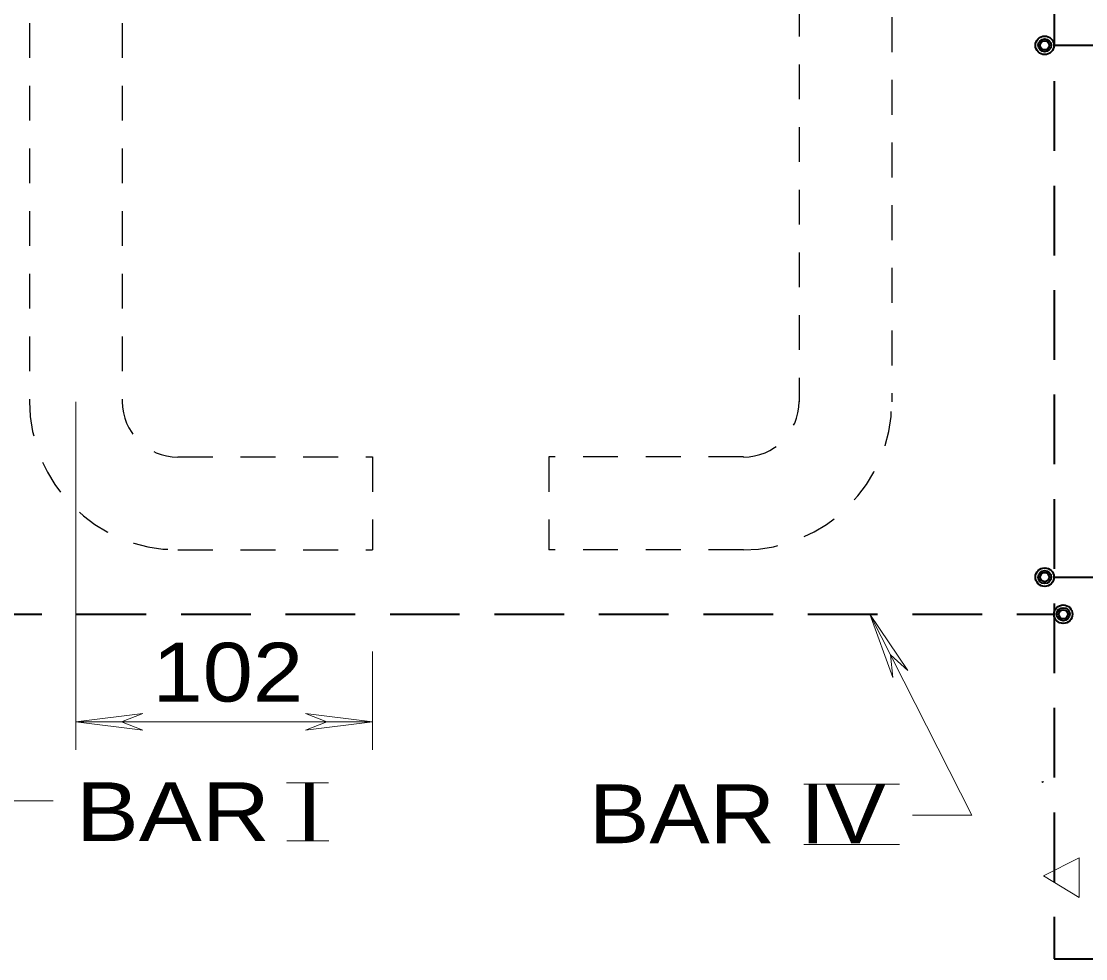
# Model space of a CAD drawing. Extents: x 312583 to 312854, y 144419 to 144597.
# Drawn here: x 312630.16 to 312643.91, y 144452.38 to 144464.5 of the extents above; entities that cross this region are included whole.
import ezdxf

# ---------------------------------------------------------------- set-up
doc = ezdxf.new("R2010")
doc.units = 0
doc.header["$LTSCALE"] = 0.3
doc.linetypes.add('MEDIUM_DASHED', pattern=[4.5, 3, -1.5])
doc.linetypes.add('SHORT_DASHED', pattern=[2.7, 1.5, -1.2])
doc.layers.add('1', color=7, linetype='Continuous', lineweight=25)
doc.layers.add('2', color=7, linetype='Continuous', lineweight=13)

msp = doc.modelspace()

# ---------------------------------------------------------------- linework, layer by layer
at = {"layer": '1', "linetype": 'SHORT_DASHED'}
for p, q in [((312630.2668, 144492.8238), (312630.2668, 144459.5811)), ((312631.4628, 144492.8238), (312631.4628, 144459.5811)), ((312640.2105, 144490.6694), (312640.2105, 144459.5811)), ((312641.4065, 144490.4701), (312641.4065, 144459.5811)), ((312632.1835, 144458.8681), (312634.6981, 144458.8681)), ((312634.6981, 144458.8681), (312634.6981, 144457.6644)), ((312636.9751, 144458.8681), (312636.9751, 144457.6644)), ((312639.4898, 144458.8681), (312636.9751, 144458.8681)), ((312632.1835, 144457.6644), (312634.6981, 144457.6644)), ((312639.4898, 144457.6644), (312636.9751, 144457.6644))]:
    msp.add_line(p, q, dxfattribs=at)
at = {"layer": '1', "linetype": 'MEDIUM_DASHED', "lineweight": 40}
for p, q in [((312643.5071, 144492.0724), (312643.5071, 144452.3821)), ((312643.5071, 144464.1888), (312667.7031, 144464.1888)), ((312643.5071, 144457.3118), (312667.7031, 144457.3118)), ((312628.1738, 144456.8364), (312643.5071, 144456.8364)), ((312643.5071, 144452.3821), (312667.7031, 144452.3821))]:
    msp.add_line(p, q, dxfattribs=at)
at = {"layer": '1', "lineweight": 13}
for p, q in [((312643.3461, 144454.6744), (312643.3538, 144454.6591)), ((312643.3538, 144454.6591), (312643.3691, 144454.6744))]:
    msp.add_line(p, q, dxfattribs=at)
msp.add_lwpolyline([(312643.8291, 144453.1718), (312643.8291, 144453.6854), (312643.3691, 144453.4554)], close=True, dxfattribs=at)
at = {"layer": '1', "lineweight": 40}
for centre, radius in [((312643.3835, 144464.1868), 0.1198), ((312643.3835, 144464.1868), 0.0838), ((312643.3835, 144464.1868), 0.0587), ((312643.3835, 144457.3137), 0.1198), ((312643.3835, 144457.3137), 0.0838), ((312643.3835, 144457.3137), 0.0587), ((312643.6231, 144456.8345), 0.1198), ((312643.6231, 144456.8345), 0.0838), ((312643.6231, 144456.8345), 0.0587)]:
    msp.add_circle(centre, radius, dxfattribs=at)
at = {"layer": '1', "linetype": 'SHORT_DASHED'}
for centre, radius, start, end in [((312632.1825, 144459.584), 1.9167, 180, 270), ((312632.1825, 144459.584), 0.7188, 180, 270), ((312639.4908, 144459.584), 1.9167, 270, 0), ((312639.4908, 144459.584), 0.7188, 270, 0)]:
    msp.add_arc(centre, radius, start, end, dxfattribs=at)
at = {"layer": '2'}
for p, q in [((312630.8648, 144459.5811), (312630.8648, 144455.0834)), ((312641.1228, 144456.8364), (312641.4218, 144456.0161)), ((312641.1228, 144456.8364), (312641.6135, 144456.1081)), ((312634.6981, 144456.3532), (312634.6981, 144455.0834)), ((312641.4218, 144456.0161), (312641.3911, 144456.3074)), ((312641.6135, 144456.1081), (312641.3911, 144456.3074)), ((312630.8648, 144455.4425), (312631.7311, 144455.5499)), ((312631.7311, 144455.5499), (312631.4551, 144455.4425)), ((312633.8318, 144455.5499), (312634.1078, 144455.4425)), ((312634.6981, 144455.4425), (312633.8318, 144455.5499)), ((312630.8648, 144455.4425), (312634.6981, 144455.4425)), ((312630.8648, 144455.4425), (312631.7311, 144455.3352)), ((312631.7311, 144455.3352), (312631.4551, 144455.4425)), ((312633.8318, 144455.3352), (312634.1078, 144455.4425)), ((312634.6981, 144455.4425), (312633.8318, 144455.3352)), ((312633.5862, 144454.6567), (312634.1306, 144454.6567)), ((312640.2718, 144454.6401), (312641.5061, 144454.6401)), ((312628.1738, 144454.4214), (312630.5735, 144454.4214)), ((312633.5907, 144453.9057), (312634.1351, 144453.9057)), ((312640.2718, 144453.8599), (312641.5061, 144453.8599))]:
    msp.add_line(p, q, dxfattribs=at)
msp.add_lwpolyline([(312641.6748, 144454.2374), (312642.4415, 144454.2374), (312641.1228, 144456.8364)], dxfattribs=at)

# ---------------------------------------------------------------- texts
for s, width, p in [('102 ', 1.15, (312631.8528, 144455.7056)), ('BAR I', 1.2, (312630.8648, 144453.9021)), ('BAR IV', 1.15, (312637.496, 144453.8752))]:
    msp.add_text(s, height=0.76, dxfattribs=dict(at, width=width)).set_placement(p)

doc.saveas('drawing.dxf')
